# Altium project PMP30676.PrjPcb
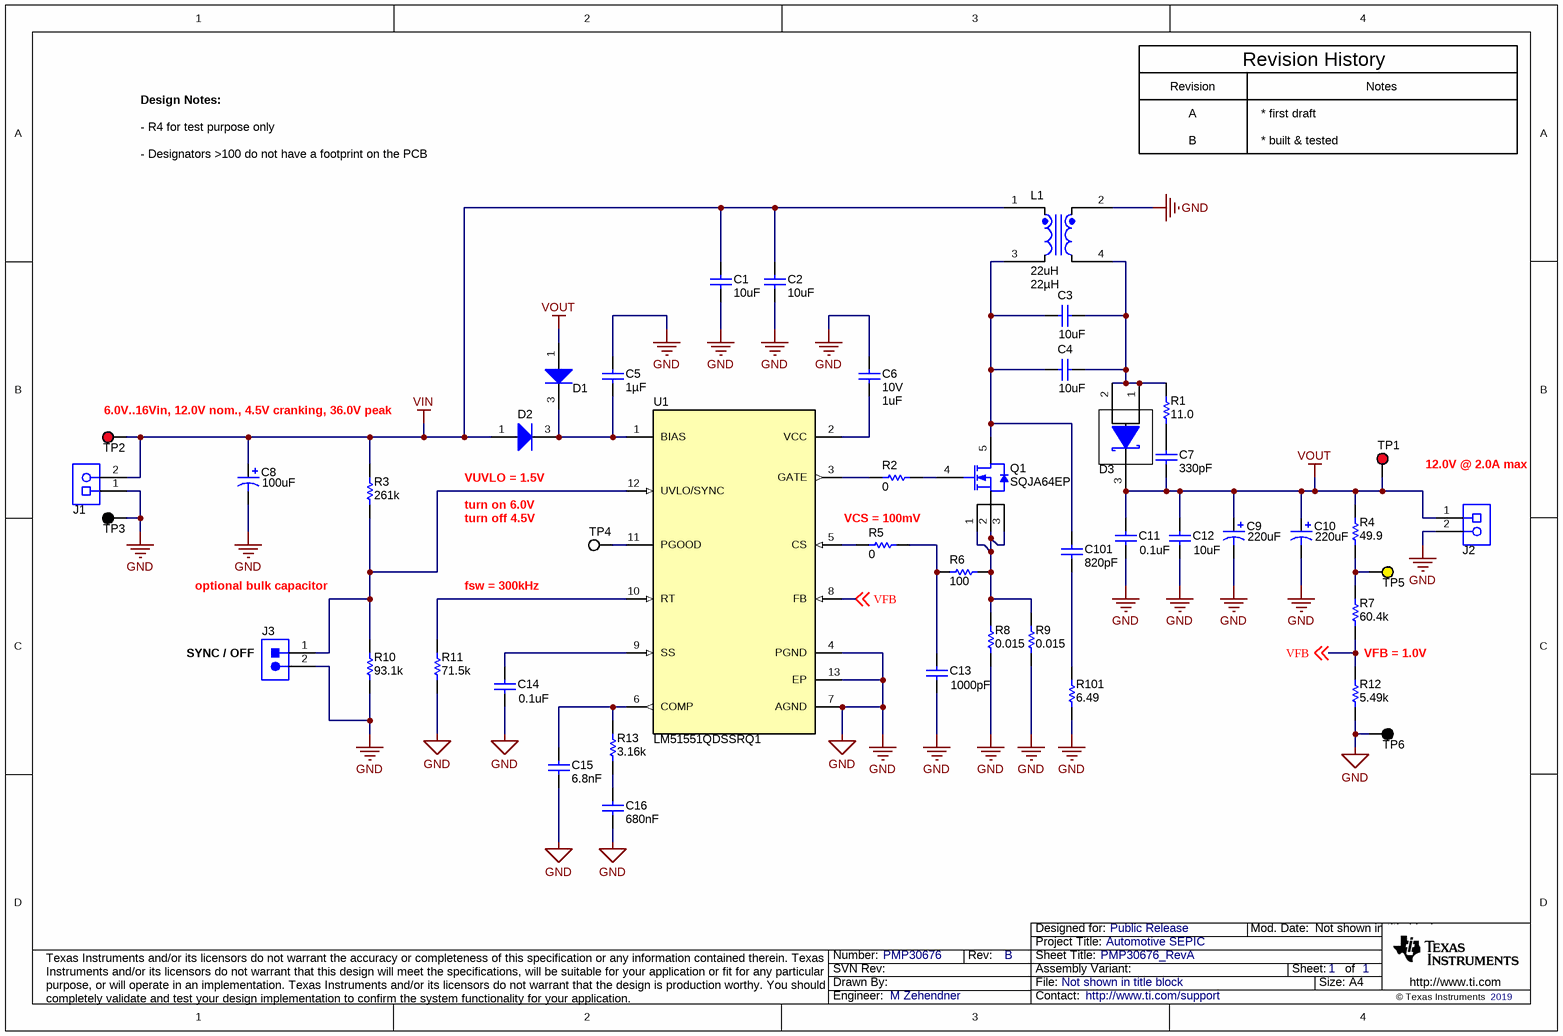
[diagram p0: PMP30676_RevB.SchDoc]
TID: N/A; TechSupport: http://www.ti.com/support; SCH_Rev: B; PRJ_Title: Automotive SEPIC; PRJ_Number: PMP30676; PRJ_Engineer: M Zehendner; PRJ_Customer: Public Release; PCB_Rev: A; PCB_Layout: M Zehendner; CopyrightYear: 2019
1 sheet, 46 parts. Net scope: global (net labels, ports and power ports of the same name join across sheets).
Board file: PMP30676.PcbDoc

## Sheet PMP30676_RevB.SchDoc: PMP30676_RevA
size A4; Date: Not shown in title block; ApprovedBy: Not shown in title block; CheckedBy: Not shown in title block; Author: Not shown in title block; CompanyName: Not shown in title block; Engineer: Not shown in title block; Organization: Not shown in title block; Address1: Not shown in title block; Address2: Not shown in title block; Address3: Not shown in title block; Address4: Not shown in title block; DocumentNumber: 1; Revision: Use project parameter SCH_Rev; SheetNumber: 1; SheetTotal: 1; PageSetup: Record=PageOptions¦CenterHorizontal=True¦CenterVertical=True¦PrintScale=0.70¦XCorrection=1.00¦YCorrection=1.00¦PrintKind=0¦BorderSize=5000000¦LeftOffset=0¦BottomOffset=0¦Orientation=2¦PaperLength=1000¦PaperWidth=1000¦Scale=100¦PaperSource=15¦PrintQuality=600¦MediaType=1¦DitherType=10¦PaperKind=A4¦PrintScaleMode=1

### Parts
C1  ValueDisplayed: 10uF  [1210_270]  (hidden comment: GRM32ER71H106KA12L)
C2  ValueDisplayed: 10uF  [1210_270]  (hidden comment: GRM32ER71H106KA12L)
C3  ValueDisplayed: 10uF  [1210_270]  (hidden comment: GRM32ER71H106KA12L)
C4  ValueDisplayed: 10uF  [1210_270]  (hidden comment: GRM32ER71H106KA12L)
C5  Cap_F: 1µF  [0805_HV]  (hidden comment: GRM21BR71H105KA12L)
C6  VDC_V: 10V  ValueDisplayed: 1uF  [0805_HV]  (hidden comment: GRM21BR71A105KA01L)
C7  Cap_F: 330pF  [0603]  (hidden comment: GRM188R71H331KA01D)
C8  ValueDisplayed: 100uF  [SM_RADIAL_G]  (hidden comment: EEE-FC1H101P)
C9  ValueDisplayed: 220uF  [HXB_HA0]  (hidden comment: HHXC250ARA221MHA0G)
C10  ValueDisplayed: 220uF  [HXB_HA0]  (hidden comment: HHXC250ARA221MHA0G)
C11  ValueDisplayed: 0.1uF  [0402]  (hidden comment: GRM155R71H104ME14D)
C12  ValueDisplayed: 10uF  [1210_220]  (hidden comment: GRM32DR71E106KA12L)
C13  ValueDisplayed: 1000pF  [0402]  (hidden comment: GRM155R61E102KA01D)
C14  ValueDisplayed: 0.1uF  [0402]  (hidden comment: GRM155R71C104KA88D)
C15  Cap_F: 6.8nF  [0603]  (hidden comment: GRM188R71E682KA01D)
C16  Cap_F: 680nF  [0603]  (hidden comment: GRM188R71A684KA61D)
C101  Cap_F: 820pF  [0603]  (hidden comment: GRM188R71H821KA01D)
D1  BAS16LT1G  [SOT-23]  (value not drawn)
D2  BAS16LT1G  [SOT-23]  (value not drawn)
D3  PDS560-13  [POWERDI5]  (value not drawn)
J1  ED120/2DS  [On-Shore_ED120_2DS]  (value not drawn)
J2  ED120/2DS  [On-Shore_ED120_2DS]  (value not drawn)
J3  TSW-102-07-G-S  [TSW-102-07-G-S]  (value not drawn)
L1  value 22uH  ValueDisplayed: 22µH  [MSD1514]  (hidden comment: MSD1514-223MEB)
Q1  SQJA64EP  [PowerPAK_SO-8L]
R1  ValueDisplayed: 11.0  [0805_HV]  (hidden comment: CRCW080511R0FKEA)
R2  ValueDisplayed: 0  [0603]  (hidden comment: ERJ-3GEY0R00V)
R3  ValueDisplayed: 261k  [0603]  (hidden comment: CRCW0603261KFKEA)
R4  ValueDisplayed: 49.9  [0603]  (hidden comment: CRCW060349R9FKEA)
R5  ValueDisplayed: 0  [0603]  (hidden comment: ERJ-3GEY0R00V)
R6  ValueDisplayed: 100  [0603]  (hidden comment: CRCW0603100RFKEA)
R7  ValueDisplayed: 60.4k  [0603]  (hidden comment: CRCW060360K4FKEA)
R8  ValueDisplayed: 0.015  [1206]  (hidden comment: CSR1206FK15L0)
R9  ValueDisplayed: 0.015  [1206]  (hidden comment: CSR1206FK15L0)
R10  ValueDisplayed: 93.1k  [0603]  (hidden comment: CRCW060393K1FKEA)
R11  ValueDisplayed: 71.5k  [0603]  (hidden comment: CRCW060371K5FKEA)
R12  ValueDisplayed: 5.49k  [0603]  (hidden comment: CRCW06035K49FKEA)
R13  ValueDisplayed: 3.16k  [0603]  (hidden comment: CRCW06033K16FKEA)
R101  ValueDisplayed: 6.49  [0603]  (hidden comment: CRCW06036R49FKEA)
TP1  5010  [Keystone5010]  (value not drawn)
TP2  5010  [Keystone5010]  (value not drawn)
TP3  5011  [Keystone5011]  (value not drawn)
TP4  5012  [Keystone5012]  (value not drawn)
TP5  5014  [Keystone5014]  (value not drawn)
TP6  5011  [Keystone5011]  (value not drawn)
U1  LM51551QDSSRQ1  [DSS0012C]

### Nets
GND: C1.2 C2.2 C5.1 C6.2 C8.2(-) C9.2(-) C10.2(-) C11.2 C12.2 C13.2 C14.2 C15.2 C16.2 J1.1 J2.2 J3.2 L1.2 R8.1 R9.1 R10.1 R11.1 R12.1 R101.1 TP3.1 TP6.1 U1.4(PGND) U1.7(AGND) U1.13(EP)
VIN: C1.1 C2.1 C8.1(+) D2.1(A) J1.2 L1.1 R3.2 TP2.1
VOUT: C7.2 C9.1(+) C10.1(+) C11.1 C12.1 D1.1(A) D3.3(K) J2.1 R4.2 TP1.1
VFB: R7.1 R12.2 U1.8(FB) ; off-sheet VFB
NetC3_1: C3.1 C4.1 D3.1(A) D3.2(A) L1.4 R1.2
NetC3_2: C3.2 C4.2 C101.1 L1.3 Q1.5(D)
NetC5_2: C5.2 D1.3(K) D2.3(K) U1.1(BIAS)
NetC6_1: C6.1 U1.2(VCC)
NetC7_1: C7.1 R1.1
NetC13_1: C13.1 R5.2 R6.1
NetC14_1: C14.1 U1.9(SS)
NetC15_1: C15.1 R13.2 U1.6(COMP)
NetC16_1: C16.1 R13.1
NetC101_2: C101.2 R101.2
NetJ3_1: J3.1 R3.1 R10.2 U1.12(UVLO/SYNC)
NetQ1_1: Q1.1(S) Q1.2(S) Q1.3(S) R6.2 R8.2 R9.2
NetQ1_4: Q1.4(G) R2.2
NetR2_1: R2.1 U1.3(GATE)
NetR4_1: R4.1 R7.2 TP5.1
NetR5_1: R5.1 U1.5(CS)
NetR11_2: R11.2 U1.10(RT)
NetTP4_1: TP4.1 U1.11(PGOOD)

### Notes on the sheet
- Design Notes:
- Revision
- A
- * first draft
- Revision History
- Notes
- - R4 for test purpose only
- - Designators >100 do not have a footprint on the PCB
- B
- * built & tested
- (near TP2) 6.0V..16Vin, 12.0V nom., 4.5V cranking, 36.0V peak
- (near D2) VUVLO = 1.5V
- turn on 6.0V
- turn off 4.5V
- VCS = 100mV
- 12.0V @ 2.0A max
- optional bulk capacitor
- fsw = 300kHz
- (near J3) SYNC / OFF
- VFB = 1.0V

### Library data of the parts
C1-C4 = CMP-0009226-3: CAP, CERM, 10 uF, 50 V, +/- 10%, X7R, 1210; Manufacturer: MuRata; TaMin_C: -55°C; Polarized: N; SizeAreaWB_mm2: 14.7; Value1: Unknown; U/M: EA; Value: 10uF; TaMax_C: 125°C; SizeZ_mm: 2.7; SizeX_mm: 3.2; SizeY_mm: 2.5; Cap_Case: 1210; Value2: 50V; SizeArea_mm2: 8; Cap_F: 10µF; AEC Category: Q200
C5 = CMP-0008350-2: CAP, CERM, 1 uF, 50 V, +/- 10%, X7R, 0805; Manufacturer: MuRata; TaMin_C: -55°C; Polarized: N; SizeAreaWB_mm2: 6.75; Value1: Unknown; U/M: EA; Value: 1uF; TaMax_C: 125°C; SizeZ_mm: 1.45; SizeX_mm: 2; SizeY_mm: 1.25; Cap_Case: 0805; Value2: 50V; SizeArea_mm2: 2.5; AEC Category: Q200
C6 = CMP-0008313-2: CAP, CERM, 1 uF, 10 V, +/- 10%, X7R, 0805; Manufacturer: MuRata; TaMin_C: -55°C; ESR_ohm: 7m; Polarized: N; SizeAreaWB_mm2: 6.75; Value1: 0.007 ohm; U/M: EA; Value: 1uF; TaMax_C: 125°C; SizeZ_mm: 1.45; SizeX_mm: 2; SizeY_mm: 1.25; Cap_Case: 0805; SizeArea_mm2: 2.5; Cap_F: 1µF; AEC Category: Q200
C7 = CMP-0007449-4: CAP, CERM, 330 pF, 50 V, +/- 10%, X7R, 0603; Manufacturer: MuRata; TaMin_C: -55°C; Polarized: N; SizeAreaWB_mm2: 4.68; Value1: Unknown; U/M: EA; Value: 330pF; TaMax_C: 125°C; SizeZ_mm: 1; SizeX_mm: 1.6; SizeY_mm: 0.8; Value2: 50V; SizeArea_mm2: 1.28; AEC Category: Q200
C8 = CMP-0011166-2: CAP, AL, 100 uF, 50 V, +/- 20%, 0.3 ohm, SMD; Manufacturer: Panasonic; TaMin_C: -40°C; ESR_ohm: 0.3; Polarized: Y; SizeAreaWB_mm2: 172.2; Value1: 0.3 ohm; U/M: EA; Value: 100uF; TaMax_C: 105°C; SizeZ_mm: 10.2; SizeX_mm: 12; SizeY_mm: 10.3; Cap_Case: G; Value2: 50V; SizeArea_mm2: 123.6; CompType: Capacitor; Cap_F: 100µF; IRMS_A: 500mA; AEC Category: Q200
C9 C10 = CMP-0012270-3: CAP, Aluminum Polymer, 220 uF, 25 V, +/- 20%, 0.027 ohm, AEC-Q200 Grade 2, D8xL10mm SMD; Manufacturer: Chemi-Con; TaMin_C: -55°C; ESR_ohm: 0.03; Polarized: Y; SizeAreaWB_mm2: 113.3; Value: 220uF; TaMax_C: 105°C; SizeZ_mm: 10.5; SizeX_mm: 9; SizeY_mm: 8.3; Cap_Case: HA0; Value2: 25V; SizeArea_mm2: 74.7; CompType: Capacitor; Cap_F: 220µF; IRMS_A: 1.6A; AEC Grade: 2; AEC Category: Q200
C11 = CMP-0006675-2: CAP, CERM, 0.1 uF, 50 V, +/- 20%, X7R, 0402; Manufacturer: MuRata; TaMin_C: -55°C; Polarized: N; SizeAreaWB_mm2: 3; Value1: Unknown; U/M: EA; Value: 0.1uF; TaMax_C: 125°C; SizeZ_mm: 0.6; SizeX_mm: 1; SizeY_mm: 0.5; Value2: 50V; Cap_F: 100nF; AEC Category: Q200
C12 = CMP-0009190-2: CAP, CERM, 10 uF, 25 V, +/- 10%, X7R, 1210; Manufacturer: MuRata; TaMin_C: -55°C; Polarized: N; SizeAreaWB_mm2: 14.7; Value1: Unknown; U/M: EA; Value: 10uF; TaMax_C: 125°C; SizeZ_mm: 2.2; SizeX_mm: 3.2; SizeY_mm: 2.5; Cap_Case: 1210; Value2: 25V; SizeArea_mm2: 8; Cap_F: 10µF; AEC Category: Q200
C13 = CMP-0006606-2: CAP, CERM, 1000 pF, 25 V, +/- 10%, X5R, 0402; Manufacturer: MuRata; TaMin_C: -55°C; Polarized: N; SizeAreaWB_mm2: 3; Value1: Unknown; U/M: EA; Value: 1000pF; TaMax_C: 85°C; SizeZ_mm: 0.6; SizeX_mm: 1; SizeY_mm: 0.5; Value2: 25V; Cap_F: 1nF; AEC Category: Q200
C14 = CMP-0006641-2: CAP, CERM, 0.1 uF, 16 V, +/- 10%, X7R, 0402; Manufacturer: MuRata; TaMin_C: -55°C; Polarized: N; SizeAreaWB_mm2: 3; Value1: Unknown; U/M: EA; Value: 0.1uF; TaMax_C: 125°C; SizeZ_mm: 0.6; SizeX_mm: 1; SizeY_mm: 0.5; Value2: 16V; Cap_F: 100nF; AEC Category: Q200
C15 = CMP-0007427-4: CAP, CERM, 6800 pF, 25 V, +/- 10%, X7R, 0603; Manufacturer: MuRata; TaMin_C: -55°C; Polarized: N; SizeAreaWB_mm2: 4.68; Value1: Unknown; U/M: EA; Value: 6800pF; TaMax_C: 125°C; SizeZ_mm: 1; SizeX_mm: 1.6; SizeY_mm: 0.8; Value2: 25V; SizeArea_mm2: 1.28; AEC Category: Q200
C16 = CMP-0007375-4: CAP, CERM, 0.68 uF, 10 V, +/- 10%, X7R, 0603; Manufacturer: MuRata; TaMin_C: -55°C; Polarized: N; SizeAreaWB_mm2: 4.68; Value1: Unknown; U/M: EA; Value: 0.68uF; TaMax_C: 125°C; SizeZ_mm: 1; SizeX_mm: 1.6; SizeY_mm: 0.8; Value2: 10V; SizeArea_mm2: 1.28; AEC Category: Q200
C101 = CMP-0007464-4: CAP, CERM, 820 pF, 50 V, +/- 10%, X7R, 0603; Manufacturer: MuRata; TaMin_C: -55°C; Polarized: N; SizeAreaWB_mm2: 4.68; Value1: Unknown; U/M: EA; Value: 820pF; TaMax_C: 125°C; SizeZ_mm: 1; SizeX_mm: 1.6; SizeY_mm: 0.8; Value2: 50V; SizeArea_mm2: 1.28; AEC Category: Q200
D1 D2 = CMP-0029193-2: Diode, Switching, 100 V, 0.2 A, SOT-23; Manufacturer: ON Semiconductor; Value: 100V; Green_Lifecycle: Active; SizeAreaWB_mm2: 14; Vf_V: 1.25V; SizeZ_mm: 1.1; AEC Qualified: N; SizeX_mm: 2.5; Green_REACh: Passed; AEC Category: Q101; Value1: 0.2A; SizeY_mm: 3; SizeArea_mm2: 7.5; Io_A: 200mA; TJmax_C: 150°C
D3 = CMP-0028523-2: Diode, Schottky, 60 V, 5 A, PowerDI5; Manufacturer: Diodes Inc.; Value2: 0.67V; Green_REACh: Passed; SizeX_mm: 6.4; SizeArea_mm2: 24.96; SizeZ_mm: 1.05; Io_A: 5A; Vf_V: 670mV; Vr_V: 60V; SizeY_mm: 3.9; SizeAreaWB_mm2: 49.56; Value: 60V; Green_Lifecycle: Active; TJmax_C: 150°C; AEC Category: Q101
J1 J2 = CMP-0074910-1: Terminal Block, 5.08 mm, 2x1, Brass, TH; Manufacturer: On-Shore Technology; Cert_VDE: Y; CNHeader: False; Current_A: 15A; Green_Lifecycle: Not Set; Shrouded: N; Gender: Female; Green_REACh: Incomplete; Voltage_V: 300V; Row_Count: 1; Pitch_mm: 5.08; CT: True
J3 = CMP-0075405-2: Header, 100mil, 2x1, Gold, TH; Manufacturer: Samtec; Pitch_mm: 2.54; Cert_VDE: N; Gender: Male; Cert_CSA: Y; Voltage_V: 550V; Green_REACh: Passed; Current_A: 6.3A; Green_Lifecycle: Active; Row_Count: 1
L1 = CMP-0080785-1: Coupled inductor, 22 µH, 11 A, 0.031 ohm, SMD; Manufacturer: Coilcraft; SizeAreaWB_mm2: 289; DCR_ohm: 0.031; SizeZ_mm: 14.2; SizeX_mm: 15; SizeArea_mm2: 225; AEC Qualified: N; AEC Category: Q200
Q1 = CMP-0000880-1: MOSFET, N-CH, 60 V, 15 A, AEC-Q101, PowerPAK_SO-8L; Alternate Manufacturer: None; Manufacturer: Vishay-Siliconix; SizeZ_mm: 1.14; ChType: N; Value2: 18 nC; Value1: 0.01; VdsMax_V: 60V; SizeX_mm: 6.15; SizeAreaWB_mm2: 58.1095; SizeY_mm: 5.13; Vgs_V: 20V; QgTyp_nC: 18; AEC Qualified: Y; Value: 60V; Rdson45_ohm: 0.016; SizeArea_mm2: 31.5495; AEC Category: Q101; IdsMax_A: 15A; U/M: EA
R1 = CMP-0020863-3: RES, 11.0, 1%, 0.125 W, AEC-Q200 Grade 0, 0805; Manufacturer: Vishay-Dale; Power_W: 125mW; TempCo: 100 ppm/C; Value_Code: 11R0; Value: 11.0; EIA_Code: E96; Res_ohm: 11; SizeX_mm: 2; SizeY_mm: 1.25; SizeZ_mm: 1.45; Value2: 0.125W; SizeArea_mm2: 2.5; AEC Qualified: Y; VDC_V: 150V; AEC Category: Q200; AEC Grade: 0
R2 R5 = CMP-0025874-4: RES, 0, 5%, 0.1 W, AEC-Q200 Grade 0, 0603; Manufacturer: Panasonic; Power_W: 100mW; TempCo: 600 ppm/C; Value_Code: 0000; Value: 0; EIA_Code: E24; SizeX_mm: 1.6; SizeY_mm: 0.8; SizeZ_mm: 1; Value2: 0.1W; SizeArea_mm2: 1.28; AEC Qualified: Y; VDC_V: 50V; AEC Category: Q200; SizeAreaWB_mm2: 4.68
R3 = CMP-0022244-4: RES, 261 k, 1%, 0.1 W, AEC-Q200 Grade 0, 0603; Manufacturer: Vishay-Dale; Power_W: 100mW; TempCo: 100 ppm/C; Value: 261k; EIA_Code: E96; SizeX_mm: 1.6; SizeY_mm: 0.8; SizeZ_mm: 1; Value2: 0.1W; SizeArea_mm2: 1.28; AEC Qualified: Y; VDC_V: 75V; AEC Category: Q200; AEC Grade: 0
R4 = CMP-0022448-4: RES, 49.9, 1%, 0.1 W, AEC-Q200 Grade 0, 0603; Manufacturer: Vishay-Dale; Power_W: 100mW; TempCo: 100 ppm/C; Value_Code: 49R9; Value: 49.9; EIA_Code: E96; SizeX_mm: 1.6; SizeY_mm: 0.8; SizeZ_mm: 1; Value2: 0.1W; SizeArea_mm2: 1.28; AEC Qualified: Y; VDC_V: 75V; AEC Category: Q200; AEC Grade: 0
R6 = CMP-0021991-2: RES, 100, 1%, 0.1 W, 0603; Manufacturer: Vishay-Dale; Power_W: 100mW; TempCo: 100 ppm/C; Value_Code: 100R; U/M: EA; Value: 100; EIA_Code: E96; SizeX_mm: 1.6; SizeY_mm: 0.8; SizeZ_mm: 1; Value2: 0.1W; SizeArea_mm2: 1.28; VDC_V: 75V; AEC Category: Q200
R7 = CMP-0022532-4: RES, 60.4 k, 1%, 0.1 W, AEC-Q200 Grade 0, 0603; Manufacturer: Vishay-Dale; Power_W: 100mW; TempCo: 100 ppm/C; Value_Code: 60k4; Value: 60.4k; EIA_Code: E96; SizeX_mm: 1.6; SizeY_mm: 0.8; SizeZ_mm: 1; Value2: 0.1W; SizeArea_mm2: 1.28; AEC Qualified: Y; VDC_V: 75V; AEC Category: Q200; AEC Grade: 0
R8 R9 = CMP-0017258-2: RES, 0.015, 1%, 0.5 W, 1206; Manufacturer: Stackpole Electronics Inc; Power_W: 500mW; TempCo: 100 ppm/C; Value_Code: R015; U/M: EA; Value: 0.015; EIA_Code: E96; SizeX_mm: 3.2; SizeY_mm: 1.6; SizeZ_mm: 1.35; Value2: 0.5W; SizeArea_mm2: 5.12; AEC Category: Q200
R10 = CMP-0022655-4: RES, 93.1 k, 1%, 0.1 W, AEC-Q200 Grade 0, 0603; Manufacturer: Vishay-Dale; Power_W: 100mW; TempCo: 100 ppm/C; Value_Code: 93k1; Value: 93.1k; EIA_Code: E96; SizeX_mm: 1.6; SizeY_mm: 0.8; SizeZ_mm: 1; Value2: 0.1W; SizeArea_mm2: 1.28; AEC Qualified: Y; VDC_V: 75V; AEC Category: Q200; AEC Grade: 0
R11 = CMP-0022581-4: RES, 71.5 k, 1%, 0.1 W, AEC-Q200 Grade 0, 0603; Manufacturer: Vishay-Dale; Power_W: 100mW; TempCo: 100 ppm/C; Value_Code: 71k5; Value: 71.5k; EIA_Code: E96; SizeX_mm: 1.6; SizeY_mm: 0.8; SizeZ_mm: 1; Value2: 0.1W; SizeArea_mm2: 1.28; AEC Qualified: Y; VDC_V: 75V; AEC Category: Q200; AEC Grade: 0
R12 = CMP-0022512-4: RES, 5.49 k, 1%, 0.1 W, AEC-Q200 Grade 0, 0603; Manufacturer: Vishay-Dale; Power_W: 100mW; TempCo: 100 ppm/C; Value_Code: 5k49; Value: 5.49k; EIA_Code: E96; SizeX_mm: 1.6; SizeY_mm: 0.8; SizeZ_mm: 1; Value2: 0.1W; SizeArea_mm2: 1.28; AEC Qualified: Y; VDC_V: 75V; AEC Category: Q200; AEC Grade: 0
R13 = CMP-0022373-4: RES, 3.16 k, 1%, 0.1 W, AEC-Q200 Grade 0, 0603; Manufacturer: Vishay-Dale; Power_W: 100mW; TempCo: 100 ppm/C; Value_Code: 3k16; Value: 3.16k; EIA_Code: E96; SizeX_mm: 1.6; SizeY_mm: 0.8; SizeZ_mm: 1; Value2: 0.1W; SizeArea_mm2: 1.28; AEC Qualified: Y; VDC_V: 75V; AEC Category: Q200; AEC Grade: 0
R101 = CMP-0022575-4: RES, 6.49, 1%, 0.1 W, AEC-Q200 Grade 0, 0603; Manufacturer: Vishay-Dale; Power_W: 100mW; TempCo: 100 ppm/C; Value_Code: 6R49; Value: 6.49; EIA_Code: E96; SizeX_mm: 1.6; SizeY_mm: 0.8; SizeZ_mm: 1; Value2: 0.1W; SizeArea_mm2: 1.28; AEC Qualified: Y; VDC_V: 75V; AEC Category: Q200; AEC Grade: 0
TP1 TP2 = CMP-0055147-1: Test Point, Multipurpose, Red, TH; Manufacturer: Keystone; CNHeader: FALSE; Green_Lifecycle: Active; Green_REACh: Passed; ContactFinish: Silver; CT: TRUE
TP3 TP6 = CMP-0055148-1: Test Point, Multipurpose, Black, TH; Manufacturer: Keystone; CNHeader: FALSE; Green_Lifecycle: Active; Green_REACh: Passed; ContactFinish: Silver; CT: TRUE
TP4 = CMP-0055149-1: Test Point, Multipurpose, White, TH; Manufacturer: Keystone; CNHeader: FALSE; Green_Lifecycle: Active; Green_REACh: Passed; ContactFinish: Silver; CT: TRUE
TP5 = CMP-0055151-1: Test Point, Multipurpose, Yellow, TH; Manufacturer: Keystone; CNHeader: FALSE; Green_Lifecycle: Active; Green_REACh: Passed; ContactFinish: Silver; CT: TRUE
U1 = CMP-0081541-1: Automotive Grade 2.2-MHz Wide Input Non-synchronous Boost Controller, DSS0012C (WSON-12); Alternate PartNumber: LM51551QDSSTQ1; Alternate Manufacturer: Texas Instruments; SizeAreaWB_mm2: 12; SizeZ_mm: 0.8; SizeX_mm: 2; SizeY_mm: 3; SizeArea_mm2: 6; CompType: IC; AEC Qualified: Y; AEC Category: Q200

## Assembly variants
001: not fitted FID1 FID2 FID3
